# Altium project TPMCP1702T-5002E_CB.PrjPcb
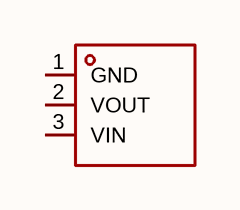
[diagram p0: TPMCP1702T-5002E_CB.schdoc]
1 sheet, 1 parts. Net scope: global (net labels, ports and power ports of the same name join across sheets).

## Sheet TPMCP1702T-5002E_CB.schdoc
size 127 x 101 mm

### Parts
U?  tpmcp1702t-5002e/cb  [SOT-23-3_L2.9-W1.6-P1.90-LS2.8-BR]  (value not drawn)

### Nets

Not connected (* = marked no-connect by the designer): U? 1(GND) 2(VOUT) 3(VIN)

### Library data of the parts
U? = tpmcp1702t-5002e/cb: 输出极性:正极;工作电压:18V;输出电压:5V;输出电流:300mA;电源纹波抑制比(PSRR):-;输出类型:固定；可调;; Manufacturer: TECH PUBLIC(台舟); AddInBom: yes; ModelId: 89cb27a44ab2466697082bb9fd73a7d0; ModelName: SOT-23-3L_L2.9-W1.6-H1.1-LS2.8-P0.95; ModelTransform: 114.173,110.236,0,90,0,0,0,0,0; Output Configuration: 正极; Voltage - Supply: 18V; Output Voltage: 5V; Output Current: 300mA; Voltage Dropout: 60mV@(40mA); standby current: 3uA; Output Type: 固定；可调; Number of Outputs: 1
